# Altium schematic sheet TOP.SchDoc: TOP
size A4; SheetNumber: 1; SheetTotal: 1
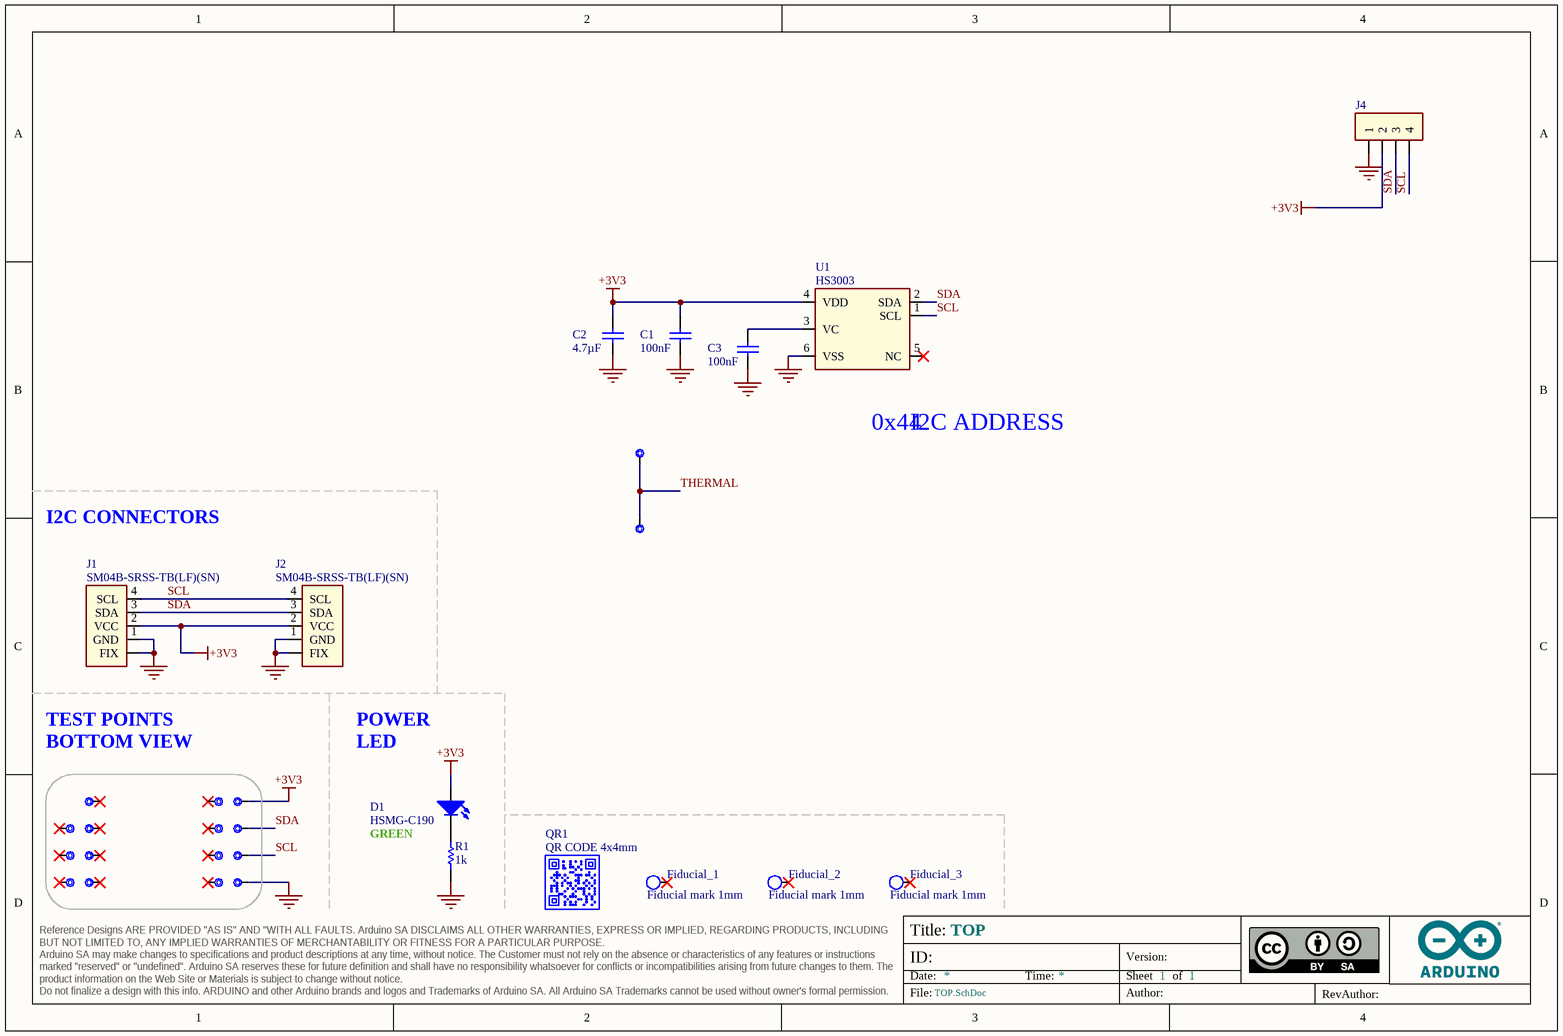
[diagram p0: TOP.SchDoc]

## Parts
3V3  Test point 1.00mm  [TP-1.00MM]  (value not drawn)  (no BOM)
C1  value 100nF  [CAP-0402]  (hidden comment: 0402B104K160CT)
C2  value 4.7µF  [CAP-0603]  (hidden comment: GRM188R61C475KAAJD)
C3  value 100nF  [CAP-0402]  (hidden comment: 0402B104K160CT)
D1  HSMG-C190  [LEDC1608X80N-AK]
Fiducial_1  Fiducial mark 1mm  [Fiducial mark 1mm-Footprint-1]  (no BOM)
Fiducial_2  Fiducial mark 1mm  [Fiducial mark 1mm-Footprint-1]  (no BOM)
Fiducial_3  Fiducial mark 1mm  [Fiducial mark 1mm-Footprint-1]  (no BOM)
GND  Test point 1.00mm  [TP-1.00MM]  (value not drawn)  (no BOM)
J1  SM04B-SRSS-TB(LF)(SN)  [SM04B-SRSS-TB(LF)(SN)-Footprint-1]
J2  SM04B-SRSS-TB(LF)(SN)  [SM04B-SRSS-TB(LF)(SN)-Footprint-1]
J4  HEADER TH 2.54mm VERT. 1x004POS  [PIN HEADER 2.54mm VERT. 1x4POS-Footprint-1]  (value not drawn)  (no BOM)
NRST  Test point 1.00mm  [TP-1.00MM]  (value not drawn)  (no BOM)
PA6  Test point 1.00mm  [TP-1.00MM]  (value not drawn)  (no BOM)
PA7  Test point 1.00mm  [TP-1.00MM]  (value not drawn)  (no BOM)
PC14  Test point 1.00mm  [TP-1.00MM]  (value not drawn)  (no BOM)
PC15  Test point 1.00mm  [TP-1.00MM]  (value not drawn)  (no BOM)
QR1  QR CODE 4x4mm  [QR CODE 4x4mm]  (no BOM)
R1  value 1k  [RES-0402]  (hidden comment: CRCW04021K00FKEDC)
SCL  Test point 1.00mm  [TP-1.00MM]  (value not drawn)  (no BOM)
SDA  Test point 1.00mm  [TP-1.00MM]  (value not drawn)  (no BOM)
SWCLK  Test point 1.00mm  [TP-1.00MM]  (value not drawn)  (no BOM)
SWDIO  Test point 1.00mm  [TP-1.00MM]  (value not drawn)  (no BOM)
THERMAL_BOTTOM  CMP-018-0004-A.4  [TP-0.8MM]  (value not drawn)  (no BOM)
THERMAL_TOP  CMP-018-0004-A.4  [TP-0.8MM]  (value not drawn)  (no BOM)
TP9  Test point 1.00mm  [TP-1.00MM]  (value not drawn)  (no BOM)
TP10  Test point 1.00mm  [TP-1.00MM]  (value not drawn)  (no BOM)
TP11  Test point 1.00mm  [TP-1.00MM]  (value not drawn)  (no BOM)
TP12  Test point 1.00mm  [TP-1.00MM]  (value not drawn)  (no BOM)
U1  HS3003  [HS3003-Footprint-1]

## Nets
+3V3: 3V3.X C1.1 C2.2 D1.A J1.2(VCC) J2.2(VCC) J4.2 U1.4(VDD)
GND: C1.2 C2.1 C3.2 GND.X J1.1(GND) J1.FIX J2.1(GND) J2.FIX J4.1 R1.1 U1.6(VSS)
SCL: J1.4(SCL) J2.4(SCL) J4.4 SCL.X U1.1(SCL)
SDA: J1.3(SDA) J2.3(SDA) J4.3 SDA.X U1.2(SDA)
THERMAL: THERMAL_BOTTOM.X THERMAL_TOP.X
NetC3_1: C3.1 U1.3(VC)
NetD1_C: D1.C R1.2

Not connected (* = marked no-connect by the designer): Fiducial_1 1*; Fiducial_2 1*; Fiducial_3 1*; NRST X*; PA6 X*; PA7 X*; PC14 X*; PC15 X*; SWCLK X*; SWDIO X*; TP9 X*; TP10 X*; TP11 X*; TP12 X*; U1 5(NC)*

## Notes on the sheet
- I2C ADDRESS
- 0x44
- I2C CONNECTORS
- TEST POINTS BOTTOM VIEW
- (near D1) POWER LED
- GREEN

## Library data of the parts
3V3 GND NRST PA6 PA7 PC14 PC15 SCL SDA SWCLK SWDIO TP9-TP12 = UT0013-A.6: Manufacturer: This is not a component
C1 C3 = C0012-A.15: CAP CHIP 0402 100nF 10% 16V X7R; Manufacturer: Walsin; Code Arduino: 0132
C2 = C0054-A.16: CAP CHIP 0603 4.7uF 10% 16V X5R; Manufacturer: Murata; Code Arduino: A5072
D1 = L0009-A.5: LED SMD 0603 GREEN/568 15mcd 120^; Manufacturer: Broadcom; Code Arduino: 2204
Fiducial_1-Fiducial_3 = UT0023-A.7: Fiducial mark 1mm clearance 2mm
J1 J2 = J0005-A.2: CONN JST 4POS SIDE 1MM TIN QWIIC; Code Arduino: J0005
J4 = J0162-A.5: Code Arduino: J0162
QR1 = QR-0001-A.2: QR CODE 4x4mm on layer 34 (This is not a component); Code Arduino: QRCODE_4x4mm
R1 = R0007-A.24: RES CHIP 0402 1k 1% 1/16W; Manufacturer: Vishay; Code Arduino: 0140; Power: 62.5mW; Temperature coefficient: 100ppm
THERMAL_BOTTOM THERMAL_TOP = UT0012-A.6: Test point 0.8mm; Manufacturer: This is not a component
U1 = U0253-A.5: IC PRESSURE AND TEMPERATURE SENSOR 6-LGA; Manufacturer: Renesas; Code Arduino: U0253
